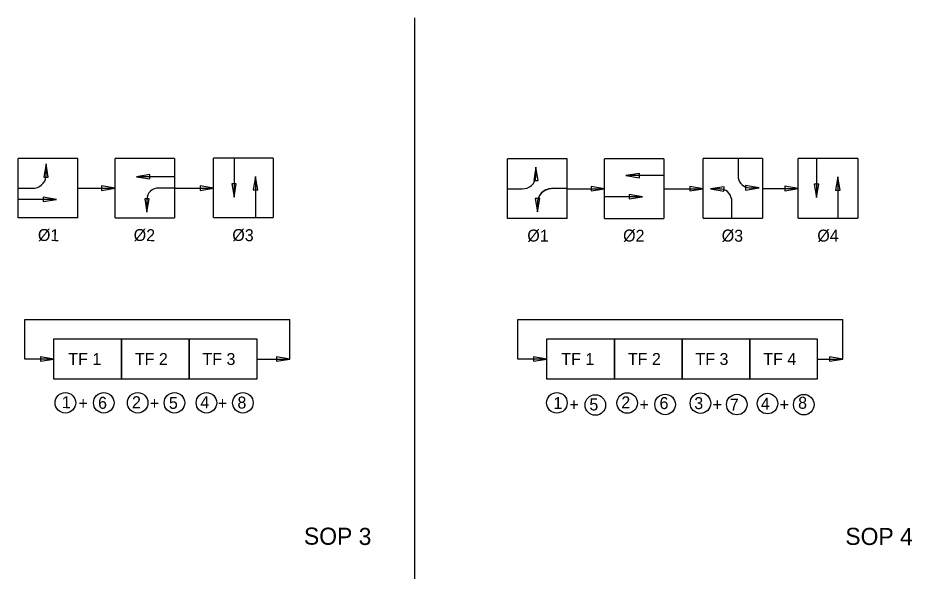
# Model space of a CAD drawing. Extents: x 10027 to 10796, y 10033 to 10528.
# Drawn here: x 10388.4 to 10649.6, y 10366.7 to 10528.4 of the extents above; entities that cross this region are included whole.
import ezdxf

# ---------------------------------------------------------------- set-up
doc = ezdxf.new("R2010")
doc.units = 0
for name, color, linetype in [('AdhocPoint_dp', 7, 'Continuous'), ('Default', 7, 'Continuous'), ('Dimension', 7, 'Continuous'), ('DSIndex', 7, 'Continuous'), ('PlotBorder_dp', 7, 'Continuous')]:
    doc.layers.add(name, color=color, linetype=linetype)

msp = doc.modelspace()

# ---------------------------------------------------------------- linework, layer by layer
at = {"layer": 'AdhocPoint_dp'}
msp.add_line((10504.32, 10205.22), (10504.32, 10528.43), dxfattribs=at)
at = {"layer": 'Default'}
for p, q in [((10405.88, 10487.35), (10388.48, 10487.35)), ((10388.48, 10469.96), (10388.48, 10487.35)), ((10396.62, 10482.17), (10396.62, 10485.78)), ((10405.88, 10469.96), (10405.88, 10487.35)), ((10416.77, 10469.96), (10416.77, 10487.35)), ((10434.16, 10487.35), (10416.77, 10487.35)), ((10434.16, 10487.35), (10434.16, 10469.96)), ((10445.57, 10470.03), (10445.57, 10487.43)), ((10462.97, 10487.43), (10445.57, 10487.43)), ((10451.54, 10487.43), (10451.54, 10476.03)), ((10462.97, 10487.43), (10462.97, 10470.03)), ((10548.81, 10487.19), (10531.41, 10487.19)), ((10531.41, 10469.79), (10531.41, 10487.19)), ((10548.81, 10469.79), (10548.81, 10487.19)), ((10559.7, 10469.79), (10559.7, 10487.19)), ((10577.1, 10487.19), (10559.7, 10487.19)), ((10577.1, 10487.19), (10577.1, 10469.79)), ((10588.5, 10469.87), (10588.5, 10487.27)), ((10605.9, 10487.27), (10588.5, 10487.27)), ((10598.78, 10487.27), (10598.78, 10481.6)), ((10605.9, 10487.27), (10605.9, 10469.87)), ((10616.3, 10469.92), (10616.3, 10487.32)), ((10633.7, 10487.32), (10616.3, 10487.32)), ((10621.63, 10487.32), (10621.63, 10475.92)), ((10633.7, 10487.32), (10633.7, 10469.92)), ((10539.7, 10482.01), (10539.7, 10484.76)), ((10539.7, 10482.01), (10539.7, 10484.76)), ((10539.7, 10482.01), (10539.7, 10484.76)), ((10539.7, 10482.01), (10539.7, 10484.76)), ((10539.7, 10482.01), (10539.7, 10484.76)), ((10539.7, 10482.01), (10539.7, 10484.76)), ((10539.7, 10482.01), (10539.7, 10484.76)), ((10539.7, 10482.01), (10539.7, 10484.76)), ((10539.7, 10482.01), (10539.7, 10484.76)), ((10539.7, 10482.01), (10539.7, 10484.76)), ((10539.7, 10482.01), (10539.7, 10484.76)), ((10539.7, 10482.01), (10539.7, 10484.76)), ((10539.7, 10482.01), (10539.7, 10484.76)), ((10539.7, 10482.01), (10539.7, 10484.76)), ((10539.7, 10482.4), (10539.7, 10484.76)), ((10434.16, 10481.99), (10423.01, 10481.99)), ((10457.78, 10482.04), (10457.78, 10470.03)), ((10539.7, 10482.01), (10539.7, 10482.43)), ((10539.7, 10482.01), (10539.7, 10482.22)), ((10576.99, 10482.31), (10565.99, 10482.31)), ((10627.86, 10481.93), (10627.86, 10469.92)), ((10388.47, 10478.66), (10392.61, 10478.66)), ((10405.88, 10478.66), (10416.77, 10478.66)), ((10434.29, 10478.66), (10429.54, 10478.66)), ((10434.16, 10478.66), (10445.57, 10478.66)), ((10531.54, 10478.49), (10535.69, 10478.49)), ((10531.54, 10478.49), (10535.69, 10478.49)), ((10531.54, 10478.49), (10535.69, 10478.49)), ((10531.54, 10478.49), (10535.69, 10478.49)), ((10531.54, 10478.49), (10535.69, 10478.49)), ((10531.54, 10478.49), (10535.69, 10478.49)), ((10531.54, 10478.49), (10535.69, 10478.49)), ((10531.54, 10478.49), (10535.69, 10478.49)), ((10531.54, 10478.49), (10535.69, 10478.49)), ((10531.54, 10478.49), (10535.69, 10478.49)), ((10531.54, 10478.49), (10535.69, 10478.49)), ((10531.54, 10478.49), (10535.69, 10478.49)), ((10531.54, 10478.49), (10535.69, 10478.49)), ((10531.54, 10478.49), (10535.69, 10478.49)), ((10531.54, 10478.49), (10535.69, 10478.49)), ((10531.54, 10478.49), (10535.69, 10478.49)), ((10548.77, 10478.51), (10544.51, 10478.51)), ((10548.77, 10478.51), (10544.63, 10478.51)), ((10548.77, 10478.51), (10544.63, 10478.51)), ((10548.77, 10478.51), (10544.63, 10478.51)), ((10548.77, 10478.51), (10544.63, 10478.51)), ((10548.77, 10478.51), (10544.63, 10478.51)), ((10548.77, 10478.51), (10544.63, 10478.51)), ((10548.77, 10478.51), (10544.63, 10478.51)), ((10548.77, 10478.51), (10544.63, 10478.51)), ((10548.77, 10478.51), (10544.63, 10478.51)), ((10548.77, 10478.51), (10544.63, 10478.51)), ((10548.77, 10478.51), (10544.63, 10478.51)), ((10548.77, 10478.51), (10544.63, 10478.51)), ((10548.77, 10478.51), (10544.63, 10478.51)), ((10548.77, 10478.51), (10544.63, 10478.51)), ((10548.77, 10478.51), (10544.63, 10478.51)), ((10548.81, 10478.49), (10559.7, 10478.49)), ((10577.1, 10478.49), (10588.5, 10478.49)), ((10605.9, 10478.57), (10616.3, 10478.57)), ((10399.67, 10475.37), (10388.4, 10475.37)), ((10426.11, 10475.37), (10426.11, 10471.61)), ((10570.86, 10476.14), (10559.7, 10476.14)), ((10596.82, 10475.56), (10596.82, 10469.89)), ((10540.14, 10474.11), (10540.14, 10471.75)), ((10540.14, 10474.11), (10540.14, 10471.75)), ((10540.14, 10474.11), (10540.14, 10471.75)), ((10540.14, 10474.11), (10540.14, 10471.75)), ((10540.14, 10474.11), (10540.14, 10471.75)), ((10540.14, 10474.11), (10540.14, 10471.75)), ((10540.14, 10474.11), (10540.14, 10471.75)), ((10540.14, 10474.11), (10540.14, 10471.75)), ((10540.14, 10474.11), (10540.14, 10471.75)), ((10540.14, 10474.11), (10540.14, 10471.75)), ((10540.14, 10474.11), (10540.14, 10471.75)), ((10540.14, 10474.11), (10540.14, 10471.75)), ((10540.14, 10474.11), (10540.14, 10471.75)), ((10540.14, 10474.11), (10540.14, 10474.04)), ((10405.88, 10469.96), (10388.48, 10469.96)), ((10416.77, 10469.96), (10434.16, 10469.96)), ((10445.57, 10470.03), (10462.97, 10470.03)), ((10588.5, 10469.87), (10605.9, 10469.87)), ((10616.3, 10469.92), (10633.7, 10469.92)), ((10548.81, 10469.79), (10531.41, 10469.79)), ((10559.7, 10469.79), (10577.1, 10469.79)), ((10390.42, 10440.22), (10467.83, 10440.22)), ((10390.42, 10428.7), (10390.42, 10440.22)), ((10467.83, 10428.7), (10467.83, 10440.22)), ((10534.4, 10440.22), (10629.31, 10440.22)), ((10534.4, 10428.7), (10534.4, 10440.22)), ((10629.31, 10428.7), (10629.31, 10440.22)), ((10398.92, 10428.7), (10390.42, 10428.7)), ((10458.46, 10428.7), (10467.83, 10428.7)), ((10542.9, 10428.7), (10534.4, 10428.7)), ((10621.88, 10428.7), (10629.31, 10428.7))]:
    msp.add_line(p, q, dxfattribs=at)
for centre, radius, start, end in [((10392.85, 10482.43), 3.78, 266.3242, 356.0955), ((10535.93, 10482.26), 3.78, 266.3242, 356.0955), ((10535.93, 10482.26), 3.78, 266.3242, 356.0955), ((10535.93, 10482.26), 3.78, 266.3242, 356.0955), ((10535.93, 10482.26), 3.78, 266.3242, 356.0955), ((10535.93, 10482.26), 3.78, 266.3242, 356.0955), ((10535.93, 10482.26), 3.78, 266.3242, 356.0955), ((10535.93, 10482.26), 3.78, 266.3242, 356.0955), ((10535.93, 10482.26), 3.78, 266.3242, 356.0955), ((10535.93, 10482.26), 3.78, 266.3242, 356.0955), ((10535.93, 10482.26), 3.78, 266.3242, 356.0955), ((10535.93, 10482.26), 3.78, 266.3242, 356.0955), ((10535.93, 10482.26), 3.78, 266.3242, 356.0955), ((10535.93, 10482.26), 3.78, 266.3242, 356.0955), ((10535.93, 10482.26), 3.78, 266.3242, 356.0955), ((10535.93, 10482.26), 3.78, 266.3242, 356.0955), ((10535.93, 10482.26), 3.78, 266.3242, 356.0955), ((10602.17, 10482.2), 3.44, 189.905, 266.8478), ((10429.33, 10475.45), 3.21, 86.1951, 181.3491), ((10544.39, 10474.25), 4.26, 84.498, 182.3266), ((10544.39, 10474.25), 4.26, 84.498, 181.8456), ((10544.39, 10474.25), 4.26, 84.498, 181.8456), ((10544.39, 10474.25), 4.26, 84.498, 181.8456), ((10544.39, 10474.25), 4.26, 84.498, 181.8456), ((10544.39, 10474.25), 4.26, 84.498, 181.8456), ((10544.39, 10474.25), 4.26, 84.498, 181.8456), ((10544.39, 10474.25), 4.26, 84.498, 181.8456), ((10544.39, 10474.25), 4.26, 84.498, 181.8456), ((10544.39, 10474.25), 4.26, 84.498, 181.8456), ((10544.39, 10474.25), 4.26, 84.498, 181.8456), ((10544.39, 10474.25), 4.26, 84.498, 181.8456), ((10544.39, 10474.25), 4.26, 88.8461, 181.8456), ((10544.39, 10474.25), 4.26, 89.8811, 181.8456), ((10544.39, 10474.25), 4.26, 90.7798, 181.8456), ((10544.39, 10474.25), 4.26, 92.6526, 181.8456), ((10593.43, 10474.96), 3.44, 9.905, 91.5208)]:
    msp.add_arc(centre, radius, start, end, dxfattribs=at)
at = {"layer": 'Dimension'}
for p, q in [((10593.34, 10478.41), (10590.71, 10478.46)), ((10601.99, 10478.76), (10604.85, 10478.77))]:
    msp.add_line(p, q, dxfattribs=at)
for centre in [(10402.28, 10415.9), (10413.49, 10415.9), (10423.4, 10415.9), (10434.13, 10415.9), (10443.47, 10415.9), (10454.12, 10415.9), (10545.83, 10415.89), (10557.06, 10415.25), (10566.35, 10415.84), (10577.43, 10415.41), (10587.75, 10415.81), (10598.35, 10415.38), (10607.33, 10415.67), (10617.92, 10415.37)]:
    msp.add_circle(centre, 3, dxfattribs=at)
at = {"layer": 'DSIndex'}
for points in [[(10398.92, 10434.57), (10418.66, 10434.57), (10418.66, 10422.82), (10398.92, 10422.82)], [(10418.66, 10434.57), (10438.41, 10434.57), (10438.41, 10422.82), (10418.66, 10422.82)], [(10438.41, 10434.57), (10458.15, 10434.57), (10458.15, 10422.82), (10438.41, 10422.82)], [(10542.9, 10434.57), (10562.64, 10434.57), (10562.64, 10422.82), (10542.9, 10422.82)], [(10562.64, 10434.57), (10582.39, 10434.57), (10582.39, 10422.82), (10562.64, 10422.82)], [(10582.39, 10434.57), (10602.13, 10434.57), (10602.13, 10422.82), (10582.39, 10422.82)], [(10602.13, 10434.57), (10621.88, 10434.57), (10621.88, 10422.82), (10602.13, 10422.82)]]:
    msp.add_lwpolyline(points, close=True, dxfattribs=at)
at = {"layer": 'PlotBorder_dp'}
for points in [[(10396.62, 10485.78), (10395.96, 10481.87), (10397.28, 10481.87)], [(10539.7, 10484.76), (10539.04, 10480.86), (10540.36, 10480.86)], [(10565.99, 10482.31), (10569.9, 10481.64), (10569.9, 10482.97)], [(10423.01, 10481.99), (10426.92, 10481.33), (10426.92, 10482.65)], [(10457.78, 10482.04), (10457.11, 10478.13), (10458.44, 10478.13)], [(10627.86, 10481.93), (10627.2, 10478.02), (10628.52, 10478.02)], [(10416.77, 10478.66), (10412.86, 10479.32), (10412.86, 10477.99)], [(10445.57, 10478.66), (10441.67, 10479.32), (10441.67, 10477.99)], [(10451.54, 10476.03), (10452.2, 10479.94), (10450.88, 10479.94)], [(10559.7, 10478.49), (10555.8, 10479.15), (10555.8, 10477.83)], [(10588.5, 10478.49), (10584.6, 10479.15), (10584.6, 10477.83)], [(10590.71, 10478.46), (10594.6, 10477.72), (10594.63, 10479.04)], [(10604.85, 10478.77), (10600.94, 10479.41), (10600.95, 10478.09)], [(10616.3, 10478.57), (10612.4, 10479.23), (10612.4, 10477.91)], [(10621.63, 10475.92), (10622.29, 10479.83), (10620.97, 10479.83)], [(10399.67, 10475.37), (10395.76, 10476.03), (10395.76, 10474.71)], [(10426.11, 10471.61), (10426.77, 10475.51), (10425.45, 10475.51)], [(10540.14, 10471.75), (10540.8, 10475.66), (10539.47, 10475.66)], [(10570.86, 10476.14), (10566.95, 10476.8), (10566.95, 10475.48)], [(10398.92, 10428.7), (10395.01, 10429.36), (10395.01, 10428.03)], [(10467.83, 10428.7), (10463.92, 10429.36), (10463.92, 10428.03)], [(10542.9, 10428.7), (10538.99, 10429.36), (10538.99, 10428.03)], [(10629.31, 10428.7), (10625.41, 10429.36), (10625.41, 10428.03)]]:
    msp.add_lwpolyline(points, close=True, dxfattribs=at)

# ---------------------------------------------------------------- texts
at = {"layer": 'Default'}
for s, p in [('TF 1', (10403.14, 10426.95)), ('TF 2', (10422.57, 10426.95)), ('TF 3', (10442.31, 10426.95)), ('TF 1', (10547.12, 10426.95)), ('TF 2', (10566.55, 10426.95)), ('TF 3', (10586.29, 10426.95)), ('TF 4', (10606.1, 10426.95))]:
    msp.add_text(s, height=3.5, dxfattribs=at).set_placement(p)
for s, p in [('SOP 3', (10471.94, 10374.44)), ('SOP 4', (10630.05, 10374.38))]:
    msp.add_text(s, height=5, rotation=359.6902, dxfattribs=at).set_placement(p)
at = {"layer": 'Dimension'}
for s, rotation, p in [('Ø1', 359.1183, (10394.23, 10463.23)), ('Ø2', 359.1183, (10422.2, 10463.23)), ('Ø3', 359.1183, (10451, 10463.23)), ('Ø1', 359.1183, (10537.16, 10463.07)), ('Ø2', 359.1183, (10565.13, 10463.07)), ('Ø3', 359.1183, (10593.93, 10463.07)), ('1', 359.6943, (10401.24, 10414.34)), ('6', 359.6943, (10411.82, 10414.16)), ('2', 359.6943, (10421.72, 10414.33)), ('5', 359.6943, (10432.5, 10414.14)), ('4', 359.6943, (10441.67, 10414.32)), ('8', 359.6943, (10452.51, 10414.23)), ('1', 359.6943, (10544.8, 10414.1)), ('2', 359.6943, (10564.62, 10414.28)), ('6', 359.6943, (10575.79, 10414.08)), ('3', 359.6943, (10585.93, 10414.06)), ('8', 359.6943, (10616.26, 10414.16)), ('5', 359.6943, (10555.3, 10413.68)), ('7', 359.6943, (10596.31, 10413.6)), ('4', 359.6943, (10605.38, 10413.91))]:
    msp.add_text(s, height=3.5, rotation=rotation, dxfattribs=at).set_placement(p)
for s, p in [('Ø4', (10621.88, 10463.02)), ('+', (10406.1, 10414.04)), ('+', (10426.94, 10414.04)), ('+', (10446.82, 10414.04)), ('+', (10549.47, 10413.67)), ('+', (10569.92, 10413.67)), ('+', (10591.3, 10413.67)), ('+', (10610.87, 10413.67))]:
    msp.add_text(s, height=3.5, dxfattribs=at).set_placement(p)

doc.saveas('drawing.dxf')
